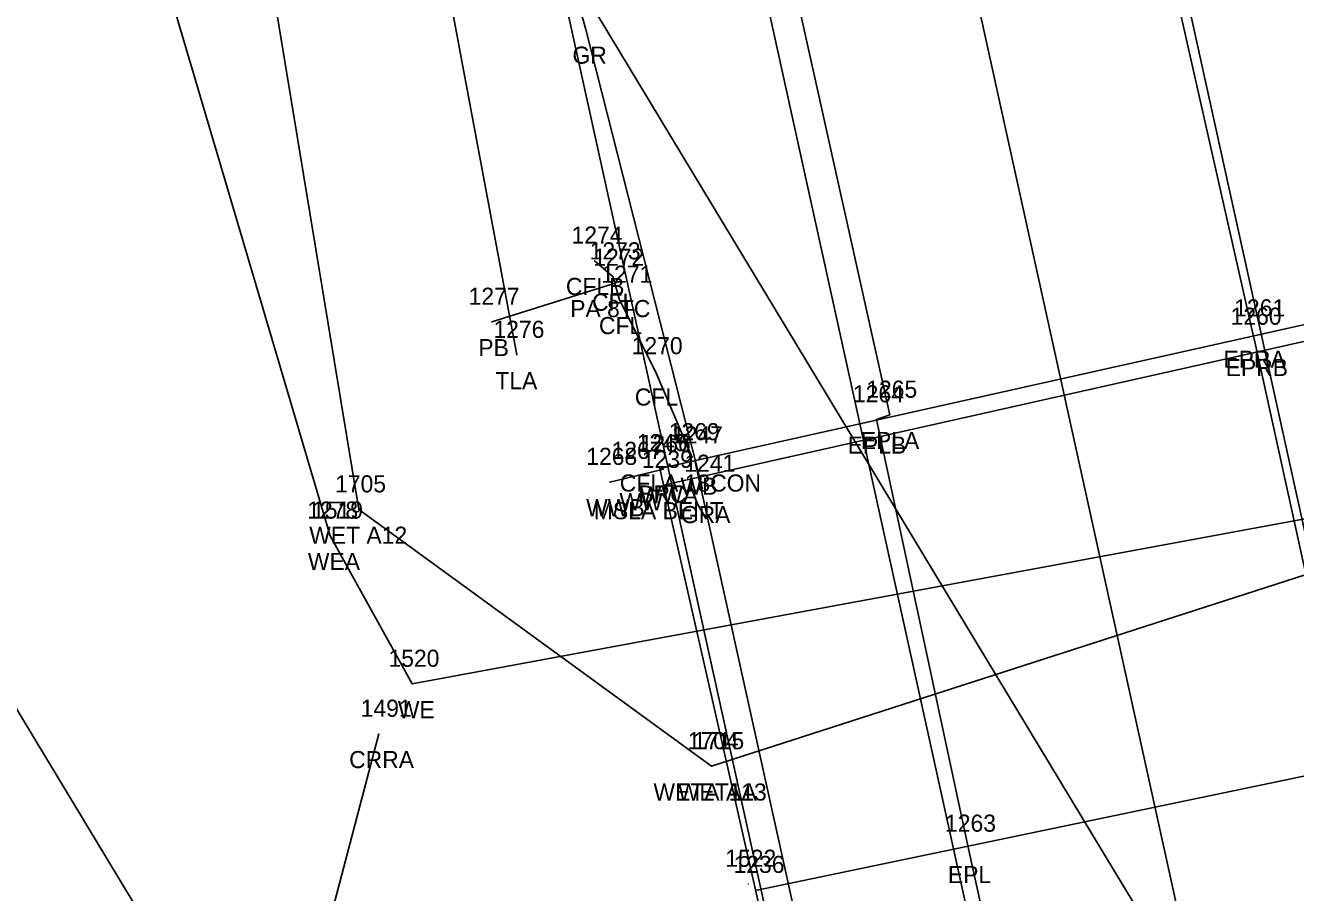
# Model space of a CAD drawing. Extents: x 2522090 to 2524658, y 882711 to 887512.
# Drawn here: x 2523721.1 to 2523795.3, y 885126.7 to 885177.3 of the extents above; entities that cross this region are included whole.
import ezdxf

# ---------------------------------------------------------------- set-up
doc = ezdxf.new("R2010")
doc.units = 0
for name, color, linetype in [('RD_EV_JurisArea', 7, 'Continuous'), ('RD_EX_BldgApp', 7, 'Continuous'), ('RD_EX_BldgApp_txCode', 7, 'Continuous'), ('RD_EX_Bridge', 7, 'Continuous'), ('RD_EX_Bridge_txCode', 7, 'Continuous'), ('RD_EX_Conc', 7, 'Continuous'), ('RD_EX_Conc_txCode', 7, 'Continuous'), ('RD_EX_DR_Pipe', 7, 'Continuous'), ('RD_EX_DR_Pipe_txCode', 7, 'Continuous'), ('RD_EX_GuardRail', 7, 'Continuous'), ('RD_EX_GuardRail_txCode', 7, 'Continuous'), ('RD_EX_H2O', 7, 'Continuous'), ('RD_EX_H2O_txCode', 7, 'Continuous'), ('RD_EX_H2O_WetLd_txCode', 7, 'Continuous'), ('RD_EX_Misc', 7, 'Continuous'), ('RD_EX_Misc_txCode', 7, 'Continuous'), ('RD_EX_Road', 7, 'Continuous'), ('RD_EX_Road_txCode', 7, 'Continuous'), ('RD_EX_VEG', 7, 'Continuous'), ('RD_EX_VEG_txCode', 7, 'Continuous'), ('RD_HC_Cl', 7, 'Continuous'), ('RD_PD_Bridge', 7, 'Continuous'), ('RD_PD_Final_TrvlWay', 7, 'Continuous'), ('RD_PD_PatLn6', 7, 'Continuous'), ('RD_SMD_Locator', 7, 'Continuous')]:
    doc.layers.add(name, color=color, linetype=linetype)

msp = doc.modelspace()

# ---------------------------------------------------------------- linework, layer by layer
at = {"layer": 'RD_EV_JurisArea'}
for points in [[(2523761.167, 885134.03), (2523740.577, 885149.032), (2523730.546, 885209.774), (2523710.597, 885357.475), (2523698.092, 885411.187), (2523674.928, 885498.624), (2523657.597, 885564.237), (2523640.817, 885610.871), (2523583.661, 885726.913), (2523539.208, 885693.17), (2523494.424, 885646.975)], [(2523761.167, 885134.03), (2523808.209, 885149.207), (2523821.914, 885178.637), (2523802.851, 885236.548), (2523777.81, 885305.562), (2523748.196, 885444.322), (2523730.68, 885516.876), (2523708.637, 885617.3), (2523698.714, 885662.019), (2523727.827, 885665.815), (2523757.297, 885671.751)]]:
    msp.add_lwpolyline(points, dxfattribs=at)
at = {"layer": 'RD_EX_BldgApp'}
msp.add_lwpolyline([(2523776.677, 885077.915), (2523768.273, 885115.309), (2523760.204, 885151.895)], dxfattribs=at)
at = {"layer": 'RD_EX_Bridge'}
for points in [[(2523774.906, 885077.596), (2523821.197, 885087.829), (2523805.064, 885161.895), (2523758.145, 885151.437), (2523774.906, 885077.596)], [(2523758.375, 885151.394), (2523756.702, 885150.987), (2523755.229, 885150.637)]]:
    msp.add_lwpolyline(points, dxfattribs=at)
at = {"layer": 'RD_EX_Conc'}
msp.add_lwpolyline([(2523760.043, 885152.079), (2523757.896, 885157.103), (2523755.804, 885161.278), (2523755.402, 885162.642), (2523754.345, 885163.563)], dxfattribs=at)
at = {"layer": 'RD_EX_DR_Pipe'}
msp.add_line((2523755.613, 885162.27), (2523748.335, 885159.99), dxfattribs=at)
at = {"layer": 'RD_EX_GuardRail'}
msp.add_lwpolyline([(2523760.648, 885150.236), (2523753.83, 885177.075), (2523749.161, 885193.784), (2523739.251, 885224.823)], dxfattribs=at)
at = {"layer": 'RD_EX_H2O'}
msp.add_line((2523738.909, 885147.498), (2523726.241, 885190.354), dxfattribs=at)
for points in [[(2523738.909, 885147.498), (2523743.695, 885138.843), (2523816.359, 885152.29), (2523822.427, 885163.299), (2523826.928, 885206.612)], [(2523741.751, 885135.924), (2523732.183, 885099.571), (2523664.897, 885060.261), (2523614.863, 885022.018), (2523558.95, 884972.63), (2523560.622, 884942.416), (2523490.005, 884911.763)]]:
    msp.add_lwpolyline(points, dxfattribs=at)
at = {"layer": 'RD_EX_Misc'}
for p, q in [((2523758.452, 885150.465), (2523805.656, 885161.063)), ((2523810.713, 885136.574), (2523763.829, 885126.803))]:
    msp.add_line(p, q, dxfattribs=at)
at = {"layer": 'RD_EX_Road'}
for p, q in [((2523792.777, 885159.311), (2523771.239, 885254.787)), ((2523771.576, 885154.562), (2523750.317, 885250.176)), ((2523792.894, 885158.826), (2523792.777, 885159.311)), ((2523798.302, 885134.145), (2523792.894, 885158.826)), ((2523770.798, 885154.293), (2523771.576, 885154.562)), ((2523776.178, 885129.21), (2523770.798, 885154.293)), ((2523781.516, 885104.768), (2523776.178, 885129.21))]:
    msp.add_line(p, q, dxfattribs=at)
at = {"layer": 'RD_EX_VEG'}
msp.add_lwpolyline([(2523749.808, 885158.06), (2523732.862, 885248.57), (2523691.618, 885438.948), (2523639.516, 885601.035)], dxfattribs=at)
at = {"layer": 'RD_HC_Cl'}
msp.add_line((2523641.165, 885794.201), (2524197.759, 883266.557), dxfattribs=at)
at = {"layer": 'RD_PD_Bridge'}
msp.add_lwpolyline([(2523748.471, 885197.618), (2523785.03, 885031.596)], dxfattribs=at)
at = {"layer": 'RD_PD_Final_TrvlWay'}
for p, q in [((2523722.39, 885481.141), (2524037.438, 884050.417)), ((2523698.951, 885475.979), (2524014, 884045.256))]:
    msp.add_line(p, q, dxfattribs=at)
at = {"layer": 'RD_PD_PatLn6'}
for p, q in [((2523748.348, 885188.144), (2523831.037, 885051.167)), ((2523705.543, 885162.303), (2523788.232, 885025.327))]:
    msp.add_line(p, q, dxfattribs=at)
at = {"layer": 'RD_SMD_Locator'}
for centre in [(2523753.83, 885177.075), (2523754.345, 885163.563), (2523755.402, 885162.642), (2523755.613, 885162.27), (2523755.804, 885161.278), (2523748.335, 885159.99), (2523792.777, 885159.311), (2523792.894, 885158.826), (2523749.808, 885158.06), (2523757.896, 885157.103), (2523770.798, 885154.293), (2523771.576, 885154.562), (2523760.043, 885152.079), (2523760.204, 885151.895), (2523758.145, 885151.437), (2523758.375, 885151.394), (2523755.229, 885150.637), (2523756.702, 885150.987), (2523758.452, 885150.465), (2523760.648, 885150.236), (2523740.577, 885149.032), (2523738.909, 885147.498), (2523738.909, 885147.498), (2523743.695, 885138.843), (2523741.751, 885135.924), (2523761.167, 885134.03), (2523761.167, 885134.03), (2523776.178, 885129.21), (2523763.322, 885127.16), (2523763.829, 885126.803)]:
    msp.add_circle(centre, 0.001, dxfattribs=at)

# ---------------------------------------------------------------- texts
at = {"layer": 'RD_EX_BldgApp_txCode'}
for s, p in [('1247', (2523758.857, 885152.895)), ('WB', (2523759.361, 885149.895)), ('1522', (2523761.976, 885128.16))]:
    msp.add_text(s, height=1, dxfattribs=at).set_placement(p)
at = {"layer": 'RD_EX_Bridge_txCode'}
for s, p in [('1245', (2523756.799, 885152.437)), ('1266', (2523756.981, 885152.394)), ('1268', (2523753.859, 885151.637)), ('1267', (2523755.332, 885151.987)), ('WWA', (2523756.981, 885149.394)), ('BRC', (2523756.893, 885149.437)), ('WWB', (2523753.851, 885148.637)), ('WW', (2523755.796, 885148.987))]:
    msp.add_text(s, height=1, dxfattribs=at).set_placement(p)
at = {"layer": 'RD_EX_Conc_txCode'}
for s, p in [('1274', (2523752.998, 885164.563)), ('1273', (2523754.056, 885163.642)), ('1271', (2523754.741, 885162.278)), ('CFLB', (2523752.668, 885161.563)), ('CFL', (2523754.197, 885160.642)), ('CFL', (2523754.599, 885159.278)), ('1270', (2523756.51, 885158.103)), ('CFL', (2523756.691, 885155.103)), ('1269', (2523758.673, 885153.079)), ('CFLA 18CON', (2523755.814, 885150.079))]:
    msp.add_text(s, height=1, dxfattribs=at).set_placement(p)
at = {"layer": 'RD_EX_DR_Pipe_txCode'}
for s, p in [('1272', (2523754.267, 885163.27)), ('1277', (2523746.988, 885160.99)), ('PA 8TC', (2523752.92, 885160.27)), ('PB', (2523747.555, 885157.99))]:
    msp.add_text(s, height=1, dxfattribs=at).set_placement(p)
at = {"layer": 'RD_EX_GuardRail_txCode'}
for s, p in [('GR', (2523753.051, 885175.075)), ('1241', (2523759.585, 885151.236)), ('GRA', (2523759.38, 885148.236))]:
    msp.add_text(s, height=1, dxfattribs=at).set_placement(p)
at = {"layer": 'RD_EX_H2O_txCode'}
for s, p in [('1278', (2523737.562, 885148.498)), ('1519', (2523737.846, 885148.498)), ('WEA', (2523737.602, 885145.498)), ('WEA', (2523737.602, 885145.498)), ('1520', (2523742.309, 885139.843)), ('1491', (2523740.688, 885136.924)), ('WE', (2523742.856, 885136.843)), ('CRRA', (2523740.011, 885133.924))]:
    msp.add_text(s, height=1, dxfattribs=at).set_placement(p)
at = {"layer": 'RD_EX_H2O_WetLd_txCode'}
for s, p in [('1705', (2523739.191, 885150.032)), ('WET A12', (2523737.679, 885147.032)), ('1704', (2523759.781, 885135.03)), ('1715', (2523760.104, 885135.03)), ('WETA A13', (2523757.781, 885132.03)), ('WET1A', (2523759.206, 885132.03))]:
    msp.add_text(s, height=1, dxfattribs=at).set_placement(p)
at = {"layer": 'RD_EX_Misc_txCode'}
for s, p in [('1239', (2523757.105, 885151.465)), ('MSLA BENT', (2523754.302, 885148.465)), ('1236', (2523762.459, 885127.803))]:
    msp.add_text(s, height=1, dxfattribs=at).set_placement(p)
at = {"layer": 'RD_EX_Road_txCode'}
for s, p in [('1260', (2523791.484, 885159.826)), ('1261', (2523791.691, 885160.311)), ('EPRA', (2523791.061, 885157.311)), ('EPRB', (2523791.193, 885156.826)), ('1264', (2523769.428, 885155.293)), ('1265', (2523770.206, 885155.562)), ('EPLA', (2523769.883, 885152.562)), ('EPLB', (2523769.121, 885152.293)), ('1263', (2523774.808, 885130.21)), ('EPL', (2523774.974, 885127.21))]:
    msp.add_text(s, height=1, dxfattribs=at).set_placement(p)
at = {"layer": 'RD_EX_VEG_txCode'}
for s, p in [('1276', (2523748.438, 885159.06)), ('TLA', (2523748.548, 885156.06))]:
    msp.add_text(s, height=1, dxfattribs=at).set_placement(p)

doc.saveas('drawing.dxf')
